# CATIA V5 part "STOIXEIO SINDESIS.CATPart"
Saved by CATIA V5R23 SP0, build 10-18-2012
Part number: ΣΤΟΙΧΕΙΟ ΣΥΝΔΕΣΗΣ 1
Bounding box of the stored display mesh (mm): x -0.5 to 1.5, y -1 to 16, z 0 to 50
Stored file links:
  G:\STOIXEIO_SINDESIS\STOIXEIO SINDESIS.CATPart
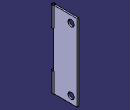
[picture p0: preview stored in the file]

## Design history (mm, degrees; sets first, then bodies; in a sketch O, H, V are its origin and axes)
WSupportSet1: ActiveGrid {3dwsupport RefPoint {point stored without definition}, 3DWOS ({wsupport Support xy-plane, RefPoint {3dwsupport}, GridIn {cartgrid Value 100, Stepbid1 0, Value 100, Stepbid2 0, Direction (1, 0, 0), Value 1000, Value 1000, LabelHeight 8}, GeometricData ({line type PtDir, Direction (1, 0, 0), Support xy-plane}; {line type PtDir, Direction (0, 1, 0), Support yz-plane})}; {wsupport Support yz-plane, RefPoint {3dwsupport}, GridIn {cartgrid Value 100, Stepbid1 0, Value 100, Stepbid2 0, Direction (0, 1, 0), Value 1000, Value 1000, LabelHeight 8}, GeometricData ({line type PtDir, Direction (0, 1, 0), Support yz-plane}; {line type PtDir, Direction (0, 0, 1), Support zx-plane})}; {wsupport Support zx-plane, RefPoint {3dwsupport}, GridIn {cartgrid Value 100, Stepbid1 0, Value 100, Stepbid2 0, Direction (0, 0, 1), Value 1000, Value 1000, LabelHeight 8}, GeometricData ({line type PtDir, Direction (0, 0, 1), Support zx-plane}; {line type PtDir, Direction (1, 0, 0), Support xy-plane})}), GeometricData ({line type PtDir, RefPoint {point stored without definition}, Direction (1, 0, 0), Support xy-plane}; {line type PtDir, RefPoint {point stored without definition}, Direction (0, 1, 0), Support yz-plane}; {line type PtDir, RefPoint {point stored without definition}, Direction (0, 0, 1), Support zx-plane})}
AxisSystem1: origin (0, 0, 0), X (1, 0, 0), Y (0, 1, 0), Z (0, 0, 1)
Body1 (main body)
  Sketch1 on yz-plane, origin (0, 0, 0), H (0, 1, 0), V (0, 0, 1)
    line L1 (0, 0) -> (16, 0)
    line L2 (16, 0) -> (16, 50)
    line L3 (16, 50) -> (0, 50)
    line L4 (0, 50) -> (0, 0)
    circle A1 centre (12, 45.5) radius 2.1
    circle A2 centre (12, 4.5) radius 2.1
    horizontal: L1 H, L3 H
    vertical: L2 V, L4 V
  Pad1: profile Sketch1, direction (1, 0, 0), length 1
  Sketch2 on xy-plane, origin (0, 0, 0), H (1, 0, 0), V (0, 1, 0)
    circle A1 centre (0.5, 0) radius 1
  Pad2: profile Sketch2, direction (0, 0, 1), length 13
  Sketch3 on face of Pad1 from Sketch1.L3, origin (0, 0, 50), H (1, 0, 0), V (0, 1, 0)
    circle A1 centre (0.5, 0) radius 1
    point P1 (0.5, 0)
    coincidence: P1 H
  Pad3: profile Sketch3, direction (0, 0, -1), length 13
  Sketch4 on end face of Pad3, origin (-0.2071, -0.7071, 37), H (1, 0, 0), V (0, -1, 0)
    point P1 (0.7071, -0.7071)
    reference projected circle E1 centre (0.7071, -0.7071) radius 1 from edge [end face of Pad3 | face of Pad3 from Sketch3.A1]
    concentricity: E1 P1
  Hole1: placed by Sketch4, at (0.5, 0, 37) direction (0, 0, 1), diameter 1.5, through (limit type 3)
